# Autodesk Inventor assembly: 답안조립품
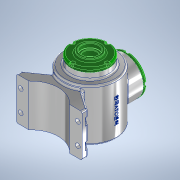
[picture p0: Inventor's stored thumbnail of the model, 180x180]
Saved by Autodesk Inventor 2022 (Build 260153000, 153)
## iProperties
Created: 2023-04
Part Number: 답안조립품
Document SubType Name: Assembly
Designer: Admin
Author: Admin
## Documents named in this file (3)
- C:\Users\Admin\Desktop\730411V1005\답안조립품.iam
- C:\Users\Admin\Desktop\730411V1005\본체.ipt
- C:\Users\Admin\Desktop\730411V1005\커버.ipt
